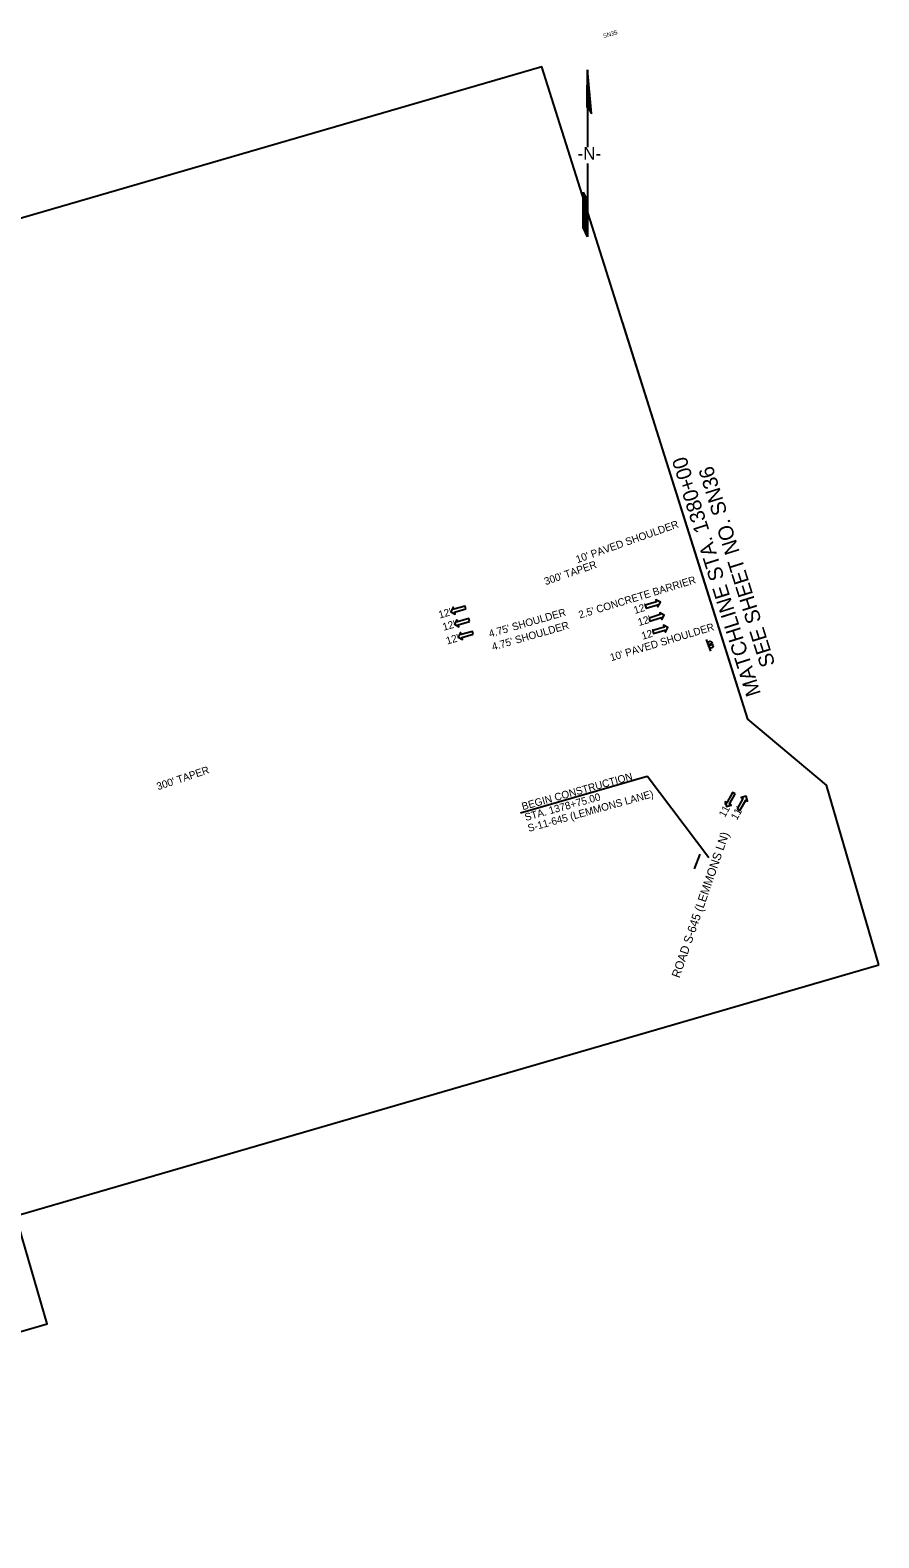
# Model space of a CAD drawing. Extents: x 1785526 to 1787270, y 1181356 to 1182767.
# Drawn here: x 1786476 to 1787270, y 1181356 to 1182767 of the extents above; entities that cross this region are included whole.
import ezdxf

# ---------------------------------------------------------------- set-up
doc = ezdxf.new("R2010")
doc.units = 0
for name, color, linetype in [('RD_EX_Road', 7, 'Continuous'), ('RD_PD_Final_LnLine', 7, 'Continuous'), ('RD_PD_Final_TX', 7, 'Continuous'), ('RD_SHT_MatchLine', 7, 'Continuous'), ('RD_SHT_ShtClip', 7, 'Continuous'), ('RD_SHT_TX', 7, 'Continuous'), ('RD_Sketch1', 7, 'Continuous'), ('RD_TX_RoadID', 7, 'Continuous'), ('SN_P_Signs', 7, 'Continuous')]:
    doc.layers.add(name, color=color, linetype=linetype)

# ---------------------------------------------------------------- blocks, each defined once
blk = doc.blocks.new('NA5')
at = {"layer": 'RD_Sketch1'}
for p, q in [((47.5, 65.9), (26.8, 37.4)), ((26.8, 30.6), (47.5, 65.9)), ((27.2, 37.5), (14.5, 19.8)), ((28.1, 38.3), (26.8, 30.6)), ((14.5, 19.8), (5.5, 7.2)), ((-3.5, -5.3), (-18.5, -26.3)), ((-18.5, -26.3), (-43.3, -60.9)), ((-30.6, -36.2), (-22.3, -24.7)), ((-22.3, -24.7), (-24, -34)), ((-41.6, -51.6), (-30.6, -36.2)), ((-43.3, -60.9), (-41.6, -51.6))]:
    blk.add_line(p, q, dxfattribs=at)
for points in [[(27.4, 37.8), (47.4, 65.8)], [(27.6, 37.9), (46.9, 64.9)], [(27.8, 38.1), (46.4, 64)], [(27.8, 36.8), (42.2, 56.8)], [(27.9, 37.4), (43.8, 59.5)], [(27.9, 37.2), (43.2, 58.6)], [(27.9, 37), (42.7, 57.7)], [(28, 38.1), (45.3, 62.2)], [(28, 37.9), (44.8, 61.3)], [(28, 37.7), (44.3, 60.4)], [(28.1, 38.3), (45.8, 63.1)], [(27.1, 37.6), (39.2, 54.5)], [(27.3, 33.9), (34.8, 44.3)], [(27.3, 33.7), (34.3, 43.4)], [(27.3, 33.4), (33.8, 42.5)], [(27.4, 34.5), (36.4, 47)], [(27.4, 34.3), (35.9, 46.1)], [(27.4, 34.1), (35.4, 45.2)], [(27.5, 34.9), (37.5, 48.8)], [(27.5, 34.7), (36.9, 47.9)], [(27.6, 35.5), (39, 51.5)], [(27.6, 35.3), (38.5, 50.6)], [(27.6, 35.1), (38, 49.7)], [(27.7, 36.2), (40.6, 54.2)], [(27.7, 36), (40.1, 53.3)], [(27.7, 35.8), (39.6, 52.4)], [(27.8, 36.6), (41.7, 56)], [(27.8, 36.4), (41.1, 55.1)], [(26.8, 30.7), (27, 30.9)], [(26.9, 37.5), (29.9, 41.7)], [(26.9, 31.3), (28.5, 33.6)], [(26.9, 31.1), (28, 32.7)], [(26.9, 30.9), (27.5, 31.8)], [(27, 32), (30.1, 36.3)], [(27, 31.8), (29.6, 35.4)], [(27, 31.5), (29.1, 34.5)], [(27.1, 32.6), (31.7, 39)], [(27.1, 32.4), (31.2, 38.1)], [(27.1, 32.2), (30.6, 37.2)], [(27.2, 33.2), (33.3, 41.6)], [(27.2, 33), (32.7, 40.7)], [(27.2, 32.8), (32.2, 39.9)], [(-42.2, -54.8), (-22.9, -27.9)], [(-42.2, -55), (-23, -28.2)], [(-42.1, -54.4), (-22.8, -27.5)], [(-42.1, -54.6), (-22.9, -27.7)], [(-42, -53.7), (-22.7, -26.8)], [(-42, -53.9), (-22.7, -27.1)], [(-42, -54.2), (-22.8, -27.3)], [(-41.9, -53.3), (-22.6, -26.4)], [(-41.9, -53.5), (-22.7, -26.6)], [(-41.8, -52.6), (-22.5, -25.7)], [(-41.8, -52.8), (-22.5, -26)], [(-41.8, -53.1), (-22.6, -26.2)], [(-41.7, -52.2), (-22.4, -25.3)], [(-41.7, -52.4), (-22.5, -25.5)], [(-41.6, -51.7), (-22.3, -24.9)], [(-41.6, -52), (-22.4, -25.1)], [(-43.3, -60.8), (-24, -33.9)], [(-43.2, -60.1), (-23.9, -33.2)], [(-43.2, -60.3), (-23.9, -33.4)], [(-43.2, -60.5), (-24, -33.6)], [(-43.1, -59.7), (-23.8, -32.8)], [(-43.1, -59.9), (-23.9, -33)], [(-43, -59), (-23.7, -32.1)], [(-43, -59.2), (-23.7, -32.3)], [(-43, -59.4), (-23.8, -32.5)], [(-42.9, -58.6), (-23.6, -31.7)], [(-42.9, -58.8), (-23.7, -31.9)], [(-42.8, -58.1), (-23.5, -31.2)], [(-42.8, -58.3), (-23.6, -31.4)], [(-42.7, -57.5), (-23.4, -30.6)], [(-42.7, -57.7), (-23.5, -30.8)], [(-42.7, -57.9), (-23.5, -31)], [(-42.6, -57), (-23.3, -30.1)], [(-42.6, -57.2), (-23.4, -30.4)], [(-42.5, -56.4), (-23.2, -29.5)], [(-42.5, -56.6), (-23.2, -29.7)], [(-42.5, -56.8), (-23.3, -29.9)], [(-42.4, -55.9), (-23.1, -29)], [(-42.4, -56.1), (-23.2, -29.3)], [(-42.3, -55.3), (-23, -28.4)], [(-42.3, -55.5), (-23, -28.6)], [(-42.3, -55.7), (-23.1, -28.8)]]:
    blk.add_lwpolyline(points, dxfattribs=at)
blk.add_text('-N-', height=11.81, rotation=324.3865, dxfattribs=at).set_placement((-8.8, 3))
blk = doc.blocks.new('SARRW2')
at = {"layer": 'RD_PD_Final_LnLine'}
blk.add_lwpolyline([(-12, 1.2), (-12, -1.2), (-2.8, -1.2), (-2.8, -2.8), (0, 0), (-2.8, 2.8), (-2.8, 1.2)], close=True, dxfattribs=at)

msp = doc.modelspace()

# ---------------------------------------------------------------- linework, layer by layer
at = {"layer": 'RD_EX_Road'}
msp.add_lwpolyline([(1787102.5, 1181995.7), (1787097.2, 1181982)], dxfattribs=at)
at = {"layer": 'RD_PD_Final_TX'}
for p in [(1786934.8, 1182034.3), (1787111.1, 1181992.2)]:
    msp.add_line(p, (1787053.3, 1182068.7), dxfattribs=at)
at = {"layer": 'RD_SHT_MatchLine'}
msp.add_line((1787221.1, 1182060.4), (1787147.5, 1182122.1), dxfattribs=at)
msp.add_lwpolyline([(1787147.5, 1182122.1), (1787105.4, 1182255.3), (1787030.2, 1182493.7)], dxfattribs=at)
at = {"layer": 'RD_SHT_ShtClip'}
msp.add_lwpolyline([(1787270.1, 1181892.1), (1787221.1, 1182060.4), (1787147.5, 1182122.1), (1787105.7, 1182254.6), (1786954.9, 1182732.3), (1786954.9, 1182732.3), (1785526.2, 1182316.8), (1785665.1, 1181836.5), (1785804, 1181356.2), (1786492.1, 1181556.5), (1786462.8, 1181657.4)], close=True, dxfattribs=at)
at = {"layer": 'SN_P_Signs'}
for p, q in [((1787108.6, 1182196.5), (1787111.8, 1182188.1)), ((1787109.5, 1182194.2), (1787112.7, 1182185.7))]:
    msp.add_line(p, q, dxfattribs=at)
for centre in [(1787112.1, 1182193), (1787113, 1182190.6)]:
    msp.add_circle(centre, 2, dxfattribs=at)

# ---------------------------------------------------------------- block references
at = {"layer": 'RD_PD_Final_LnLine'}
for p, xscale, yscale, rotation in [((1787065.7, 1182231.4), 1.2, 1.2000000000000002, 16.80308723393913), ((1786869.6, 1182222.5), 1.1999999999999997, 1.2000000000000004, -163.86503620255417), ((1787069.3, 1182219.4), 1.2, 1.2000000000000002, 16.80308723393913), ((1786873, 1182210.8), 1.1999999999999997, 1.2000000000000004, -163.86503620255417), ((1786876.5, 1182198.8), 1.1999999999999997, 1.2000000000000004, -163.86503620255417), ((1787072.8, 1182207.7), 1.2, 1.2000000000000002, 16.80308723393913), ((1787127.5, 1182040.2), 1.2, 1.2000000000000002, -119.08862906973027), ((1787145.9, 1182050), 1.2, 1.2, 60.91137093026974)]:
    msp.add_blockref('SARRW2', p, dxfattribs=dict(at, xscale=xscale, yscale=yscale, rotation=rotation))
at = {"layer": 'RD_SHT_MatchLine', "rotation": 35.61349782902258}
msp.add_blockref('NA5', (1786997.2, 1182648.1), dxfattribs=at)

# ---------------------------------------------------------------- texts
at = {"layer": 'RD_PD_Final_TX'}
for s, rotation, p in [("10' PAVED SHOULDER", 19.5007, (1786988.1, 1182267.9)), ("300' TAPER", 18.9134, (1786958.4, 1182247.3)), ("2.5' CONCRETE BARRIER", 17.0093, (1786990.4, 1182216.1)), ("12'", 16.135, (1786859.3, 1182216.1)), ("4.75' SHOULDER", 16.1274, (1786906.3, 1182198.4)), ("12'", 16.8031, (1787041.9, 1182220.4)), ("12'", 16.135, (1786863.1, 1182204.7)), ("4.75' SHOULDER", 16.1274, (1786909.2, 1182186.2)), ("10' PAVED SHOULDER", 16.8031, (1787019.8, 1182176.2)), ("12'", 16.8031, (1787045.8, 1182209.1)), ("12'", 16.8031, (1787049.2, 1182196.3)), ("12'", 16.135, (1786866.3, 1182191.8)), ("300' TAPER", 18.4182, (1786595.8, 1182055.5)), ('BEGIN CONSTRUCTION', 15.5862, (1786937.1, 1182036.8)), ('STA. 1378+75.00', 15.5862, (1786939.9, 1182026.7)), ('S-11-645 (LEMMONS LANE)', 15.5862, (1786942.7, 1182016.5)), ("11'", 60.9114, (1787126, 1182029.6)), ("11'", 60.9114, (1787137.3, 1182027.1))]:
    msp.add_text(s, height=7, rotation=rotation, dxfattribs=at).set_placement(p)
at = {"layer": 'RD_SHT_MatchLine'}
for s, p in [('MATCHLINE STA. 1380+00', (1787159.9, 1182145.9)), ('SEE SHEET NO. SN36', (1787173.3, 1182173.3))]:
    msp.add_text(s, height=14, rotation=107.5135, dxfattribs=at).set_placement(p)
at = {"layer": 'RD_SHT_TX'}
msp.add_text('SN35', height=4, rotation=16.213, dxfattribs=at).set_placement((1787012.7, 1182759.1))
at = {"layer": 'RD_TX_RoadID'}
msp.add_text('ROAD S-645 (LEMMONS LN)', height=8, rotation=71.0103, dxfattribs=at).set_placement((1787083.6, 1181879.4))

doc.saveas('drawing.dxf')
